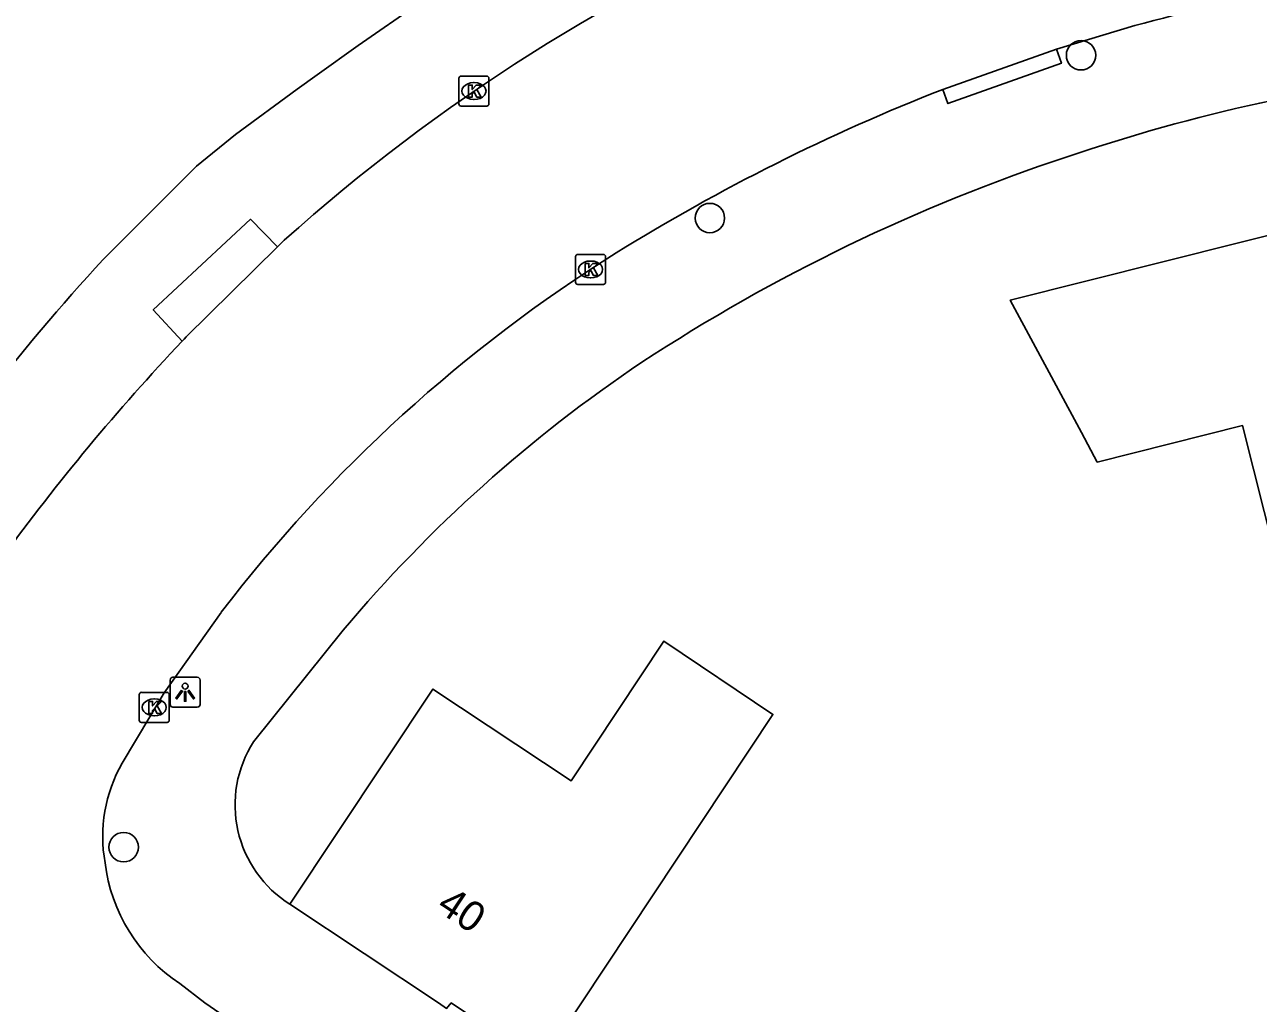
# Model space of a CAD drawing. Extents: x 163010 to 163853, y 382793 to 383982.
# Drawn here: x 163191.35 to 163232.4, y 383499.99 to 383532.53 of the extents above; entities that cross this region are included whole.
import ezdxf

# ---------------------------------------------------------------- set-up
doc = ezdxf.new("R2010")
doc.units = 0
for name, color, linetype in [('IMGEO_Boom', 7, 'Continuous'), ('IMGEO_Kolk', 7, 'Continuous'), ('IMGEO_Lichtpunt', 7, 'Continuous'), ('IMGEO_Pand', 7, 'Continuous'), ('IMGEO_Pand_nummerreeks', 7, 'Continuous'), ('IMGEO_Rijbaan_lokaal_open', 7, 'Continuous'), ('IMGEO_Voetpad_open', 7, 'Continuous')]:
    doc.layers.add(name, color=color, linetype=linetype)

msp = doc.modelspace()

# ---------------------------------------------------------------- linework, layer by layer
at = {"layer": 'IMGEO_Boom'}
for centre in [(163226.504, 383531.515), (163214.153, 383526.102), (163194.646, 383505.179)]:
    msp.add_circle(centre, 0.489, dxfattribs=at)
at = {"layer": 'IMGEO_Kolk'}
for p, q in [((163205.801, 383529.899), (163205.801, 383530.751)), ((163205.876, 383530.825), (163206.728, 383530.825)), ((163206.802, 383530.751), (163206.802, 383529.899)), ((163206.289, 383530.605), (163206.314, 383530.605)), ((163206.728, 383529.825), (163205.876, 383529.825)), ((163206.312, 383530.045), (163206.287, 383530.045)), ((163209.758, 383524.893), (163210.61, 383524.893)), ((163209.683, 383523.967), (163209.683, 383524.819)), ((163210.171, 383524.673), (163210.196, 383524.673)), ((163210.684, 383524.819), (163210.684, 383523.967)), ((163210.194, 383524.113), (163210.169, 383524.113)), ((163210.61, 383523.893), (163209.758, 383523.893)), ((163195.163, 383509.402), (163195.163, 383510.254)), ((163195.238, 383510.328), (163196.09, 383510.328)), ((163195.651, 383510.108), (163195.676, 383510.108)), ((163196.164, 383510.254), (163196.164, 383509.402)), ((163196.09, 383509.328), (163195.238, 383509.328)), ((163195.674, 383509.548), (163195.649, 383509.548))]:
    msp.add_line(p, q, dxfattribs=at)
for points in [[(163205.801, 383529.899), (163205.801, 383530.751)], [(163205.876, 383530.825), (163206.728, 383530.825)], [(163206.802, 383530.751), (163206.802, 383529.899)], [(163206.122, 383530.525), (163206.245, 383530.525), (163206.245, 383530.374), (163206.375, 383530.525), (163206.539, 383530.525), (163206.393, 383530.374), (163206.546, 383530.125), (163206.394, 383530.125), (163206.309, 383530.289), (163206.245, 383530.222), (163206.245, 383530.125), (163206.122, 383530.125), (163206.122, 383530.525)], [(163206.728, 383529.825), (163205.876, 383529.825)], [(163209.758, 383524.893), (163210.61, 383524.893)], [(163209.683, 383523.967), (163209.683, 383524.819)], [(163210.004, 383524.593), (163210.127, 383524.593), (163210.127, 383524.442), (163210.257, 383524.593), (163210.421, 383524.593), (163210.275, 383524.442), (163210.428, 383524.193), (163210.276, 383524.193), (163210.191, 383524.357), (163210.127, 383524.29), (163210.127, 383524.193), (163210.004, 383524.193), (163210.004, 383524.593)], [(163210.684, 383524.819), (163210.684, 383523.967)], [(163210.61, 383523.893), (163209.758, 383523.893)], [(163195.163, 383509.402), (163195.163, 383510.254)], [(163195.238, 383510.328), (163196.09, 383510.328)], [(163196.164, 383510.254), (163196.164, 383509.402)], [(163195.484, 383510.028), (163195.607, 383510.028), (163195.607, 383509.877), (163195.737, 383510.028), (163195.901, 383510.028), (163195.755, 383509.877), (163195.908, 383509.628), (163195.756, 383509.628), (163195.671, 383509.792), (163195.607, 383509.725), (163195.607, 383509.628), (163195.484, 383509.628), (163195.484, 383510.028)], [(163196.09, 383509.328), (163195.238, 383509.328)]]:
    msp.add_lwpolyline(points, dxfattribs=at)
for centre, start, end in [((163205.878, 383530.749), 91.552, 178.448), ((163205.878, 383530.749), 91.552, 178.448), ((163206.726, 383530.749), 1.552, 88.448), ((163206.726, 383530.749), 1.552, 88.448), ((163205.878, 383529.901), 181.552, 268.448), ((163205.878, 383529.901), 181.552, 268.448), ((163206.726, 383529.901), 271.552, 358.448), ((163206.726, 383529.901), 271.552, 358.448), ((163209.76, 383524.817), 91.552, 178.448), ((163209.76, 383524.817), 91.552, 178.448), ((163210.608, 383524.817), 1.552, 88.448), ((163210.608, 383524.817), 1.552, 88.448), ((163209.76, 383523.969), 181.552, 268.448), ((163209.76, 383523.969), 181.552, 268.448), ((163210.608, 383523.969), 271.552, 358.448), ((163210.608, 383523.969), 271.552, 358.448), ((163195.24, 383510.252), 91.552, 178.448), ((163195.24, 383510.252), 91.552, 178.448), ((163196.088, 383510.252), 1.552, 88.448), ((163196.088, 383510.252), 1.552, 88.448), ((163195.24, 383509.404), 181.552, 268.448), ((163195.24, 383509.404), 181.552, 268.448), ((163196.088, 383509.404), 271.552, 358.448), ((163196.088, 383509.404), 271.552, 358.448)]:
    msp.add_arc(centre, 0.0765, start, end, dxfattribs=at)
for centre, major_axis, ratio, start_param, end_param in [((163206.288, 383530.325), (-0.387, 0.002), 0.722429, 4.712389, 7.853982), ((163206.313, 383530.325), (-0.39, 0.002), 0.717154, 1.570796, 4.712389), ((163210.17, 383524.393), (-0.387, 0.002), 0.722429, 4.712389, 7.853982), ((163210.195, 383524.393), (-0.39, 0.002), 0.717154, 1.570796, 4.712389), ((163195.65, 383509.828), (-0.387, 0.002), 0.722429, 4.712389, 7.853982), ((163195.675, 383509.828), (-0.39, 0.002), 0.717154, 1.570796, 4.712389)]:
    msp.add_ellipse(centre, major_axis=major_axis, ratio=ratio, start_param=start_param, end_param=end_param, dxfattribs=at)
at = {"layer": 'IMGEO_Lichtpunt'}
for p, q in [((163196.192, 383510.736), (163196.192, 383509.929)), ((163196.192, 383510.736), (163196.192, 383509.929)), ((163197.094, 383510.831), (163196.286, 383510.831)), ((163197.094, 383510.831), (163196.286, 383510.831)), ((163197.188, 383509.929), (163197.188, 383510.736)), ((163197.188, 383509.929), (163197.188, 383510.736)), ((163196.286, 383509.835), (163197.094, 383509.835)), ((163196.286, 383509.835), (163197.094, 383509.835))]:
    msp.add_line(p, q, dxfattribs=at)
for points in [[(163196.566, 383510.4), (163196.605, 383510.372), (163196.417, 383510.11), (163196.379, 383510.137), (163196.566, 383510.4)], [(163196.668, 383510.352), (163196.715, 383510.352), (163196.715, 383510.03), (163196.668, 383510.03), (163196.668, 383510.352)], [(163196.778, 383510.372), (163196.816, 383510.399), (163197.003, 383510.137), (163196.964, 383510.109), (163196.778, 383510.372)]]:
    msp.add_lwpolyline(points, dxfattribs=at)
msp.add_circle((163196.691, 383510.534), 0.0994, dxfattribs=at)
for centre, start, end in [((163196.286, 383510.736), 90, 180), ((163196.286, 383510.736), 90, 180), ((163197.094, 383510.736), 0, 90), ((163197.094, 383510.736), 0, 90), ((163196.286, 383509.929), 180, 270), ((163196.286, 383509.929), 180, 270), ((163197.094, 383509.929), 270, 0), ((163197.094, 383509.929), 270, 360)]:
    msp.add_arc(centre, 0.0946, start, end, dxfattribs=at)
at = {"layer": 'IMGEO_Pand'}
for points in [[(163238.185, 383514.154), (163238.051, 383514.121), (163237.792, 383515.153), (163237.309, 383515.032), (163237.085, 383515.921), (163232.961, 383514.885), (163231.878, 383519.201), (163227.044, 383517.988), (163226.515, 383518.971), (163224.146, 383523.373), (163236.913, 383526.578), (163237.414, 383524.581), (163247.065, 383527.004), (163247.637, 383524.723), (163247.911, 383524.792), (163249.164, 383519.802), (163249.588, 383518.115), (163243.743, 383516.647), (163244.002, 383515.615), (163238.414, 383514.212), (163238.185, 383514.154)], [(163208.553, 383498), (163209.881, 383500), (163216.251, 383509.593), (163212.624, 383512.031), (163209.535, 383507.381), (163204.934, 383510.437), (163200.18, 383503.28)], [(163200.18, 383503.28), (163205.118, 383500), (163205.393, 383499.817), (163205.546, 383500), (163208.553, 383498)]]:
    msp.add_lwpolyline(points, dxfattribs=at)
at = {"layer": 'IMGEO_Rijbaan_lokaal_open'}
for points in [[(163225.687, 383531.723), (163228.29, 383532.501)], [(163221.906, 383530.379), (163225.687, 383531.723)], [(163199.988, 383525.364), (163199.767, 383525.146)], [(163199.767, 383525.146), (163196.726, 383522.148), (163196.66, 383522.079), (163196.595, 383522.01)], [(163194.6, 383507.978), (163195.988, 383510.316), (163197.888, 383512.989)], [(163212.648, 383489.419), (163211.426, 383490.304), (163197.347, 383500), (163196.511, 383500.644)]]:
    msp.add_lwpolyline(points, dxfattribs=at)
for centre, radius, start, end in [((163241.012, 383479.628), 61.439, 112.67834, 131.8916), ((163244.013, 383475.047), 59.566, 95.19346, 105.30494), ((163245.942, 383468.757), 66.144, 111.30851, 121.85111), ((163237.513, 383482.605), 49.933, 122.0205, 142.519), ((163249.308, 383472.113), 72.583, 136.57195, 143.98879), ((163198.847, 383505.534), 4.9, 150.0813, 190.2381), ((163199.627, 383505.35), 5.644, 186.9908, 236.4879)]:
    msp.add_arc(centre, radius, start, end, dxfattribs=at)
at = {"layer": 'IMGEO_Voetpad_open'}
for points in [[(163206.44, 383534.758), (163206.545, 383534.594), (163204.503, 383533.255), (163202.445, 383531.842), (163201.084, 383530.863), (163200.419, 383530.385), (163198.367, 383528.885), (163197.068, 383527.832), (163193.963, 383524.726)], [(163221.906, 383530.379), (163222.073, 383529.909), (163225.854, 383531.252), (163225.687, 383531.723)], [(163196.595, 383522.01), (163195.63, 383523.05), (163198.871, 383526.064), (163199.767, 383525.146)], [(163201.952, 383512.397), (163198.967, 383508.686)]]:
    msp.add_lwpolyline(points, dxfattribs=at)
for centre, radius, start, end in [((163245.653, 383470.2), 61.168, 96.23001, 108.69471), ((163245.063, 383470.671), 60.534, 108.30839, 123.23094), ((163248.961, 383474.182), 74.696, 137.41689, 146.98321), ((163238.324, 383481.824), 47.514, 123.8044, 139.9511), ((163202.25, 383506.583), 3.898, 147.3616, 237.9315)]:
    msp.add_arc(centre, radius, start, end, dxfattribs=at)

# ---------------------------------------------------------------- texts
at = {"layer": 'IMGEO_Pand_nummerreeks'}
msp.add_text('40', height=1, rotation=326.4064, dxfattribs=at).set_placement((163205.01, 383503.097))

doc.saveas('drawing.dxf')
